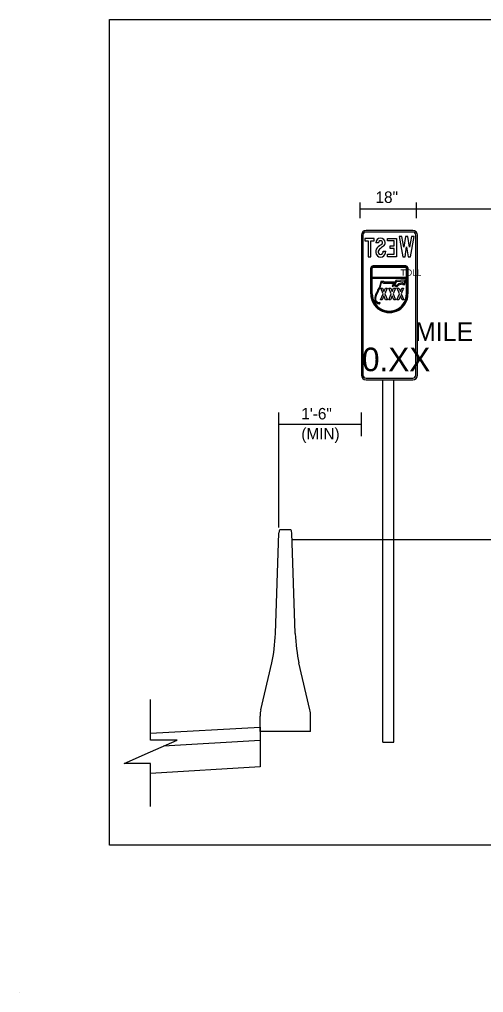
# Model space of a CAD drawing. Extents: x 57428 to 58066, y 11696 to 12105.
# Drawn here: x 57427.9 to 57541.3, y 11696.3 to 11934.3 of the extents above; entities that cross this region are included whole.
import ezdxf

# ---------------------------------------------------------------- set-up
doc = ezdxf.new("R2010")
doc.units = 0
for name, color, linetype in [('AdhocPoint_dp', 7, 'Continuous'), ('Default', 7, 'Continuous'), ('DimLines_dp', 7, 'Continuous'), ('NonPlottingEle_dp', 7, 'Continuous'), ('SignPanel', 7, 'Continuous'), ('TextMisc', 7, 'Continuous'), ('XSGrdLine_ex', 7, 'Continuous')]:
    doc.layers.add(name, color=color, linetype=linetype)

msp = doc.modelspace()

# ---------------------------------------------------------------- linework, layer by layer
at = {"layer": 'AdhocPoint_dp'}
msp.add_line((57427.89, 11696.32), (57427.89, 11696.32), dxfattribs=at)
at = {"layer": 'Default'}
msp.add_lwpolyline([(57459.93, 11741.8), (57459.93, 11752.36), (57453.47, 11752.36), (57459.93, 11755.17), (57466.39, 11757.99), (57459.93, 11757.99), (57459.93, 11767.99)], dxfattribs=at)
at = {"layer": 'DimLines_dp'}
for p, q in [((57511.19, 11885.65), (57511.19, 11889.48)), ((57511.19, 11887.93), (57524.88, 11887.93)), ((57524.88, 11885.65), (57524.88, 11889.48)), ((57524.88, 11887.93), (57585.54, 11887.93)), ((57491.3, 11810.03), (57491.3, 11838.14)), ((57511.44, 11832.39), (57511.44, 11838.14)), ((57491.3, 11835.3), (57511.44, 11835.3))]:
    msp.add_line(p, q, dxfattribs=at)
at = {"layer": 'NonPlottingEle_dp'}
for p, q in [((57516.7, 11807.11), (57516.7, 11846.15)), ((57519.36, 11807.11), (57519.36, 11846.15)), ((57516.7, 11757.53), (57516.7, 11807.11)), ((57519.36, 11757.53), (57519.36, 11807.11)), ((57516.7, 11757.53), (57519.36, 11757.53))]:
    msp.add_line(p, q, dxfattribs=at)
at = {"layer": 'SignPanel'}
for p, q in [((57515.59, 11879.64), (57514.97, 11879.64)), ((57515.59, 11879.64), (57514.97, 11879.64)), ((57515.59, 11879.64), (57514.97, 11879.64)), ((57516.78, 11877.63), (57517.41, 11877.63)), ((57516.78, 11877.63), (57517.41, 11877.63)), ((57516.78, 11877.63), (57517.41, 11877.63)), ((57513.72, 11867.13), (57513.72, 11873.41)), ((57513.91, 11867.13), (57513.91, 11873.41)), ((57514.1, 11871.13), (57514.1, 11873.41)), ((57522.27, 11873.98), (57514.29, 11873.98)), ((57522.27, 11873.79), (57514.29, 11873.79)), ((57522.27, 11873.6), (57514.29, 11873.6)), ((57522.47, 11871.13), (57522.47, 11873.41)), ((57522.65, 11867.13), (57522.65, 11873.41)), ((57522.84, 11867.13), (57522.84, 11873.41)), ((57522.47, 11871.13), (57514.1, 11871.13)), ((57514.1, 11867.13), (57514.1, 11870.94)), ((57522.47, 11870.94), (57514.1, 11870.94)), ((57522.47, 11867.13), (57522.47, 11870.94)), ((57515.84, 11868.76), (57515.38, 11868.04)), ((57515.61, 11867.97), (57516.05, 11868.67)), ((57516.17, 11870.19), (57515.84, 11868.76)), ((57516.05, 11868.67), (57516.35, 11869.97)), ((57516.9, 11870.19), (57516.17, 11870.19)), ((57516.35, 11869.97), (57516.78, 11869.97)), ((57516.78, 11869.97), (57516.89, 11869.81)), ((57516.89, 11869.81), (57519.89, 11869.81)), ((57517.01, 11870.04), (57516.9, 11870.19)), ((57519.74, 11870.04), (57517.01, 11870.04)), ((57519.44, 11869.52), (57518.94, 11869.18)), ((57518.94, 11869.18), (57519.07, 11868.99)), ((57519.07, 11868.99), (57519.45, 11869.25)), ((57520.05, 11869.16), (57519.44, 11869.52)), ((57519.45, 11869.25), (57520.08, 11868.88)), ((57519.87, 11870.39), (57519.74, 11870.04)), ((57522.25, 11870.57), (57519.87, 11870.39)), ((57519.89, 11869.81), (57520.03, 11870.17)), ((57520.03, 11870.17), (57521.98, 11870.32)), ((57520.5, 11869.58), (57520.05, 11869.16)), ((57520.08, 11868.88), (57520.62, 11869.37)), ((57521.42, 11869.88), (57520.5, 11869.58)), ((57520.62, 11869.37), (57521.38, 11869.62)), ((57520.99, 11870.23), (57520.99, 11870.23)), ((57521.38, 11869.62), (57521.63, 11869.42)), ((57521.69, 11869.66), (57521.42, 11869.88)), ((57521.63, 11869.42), (57522.08, 11869.48)), ((57521.88, 11869.69), (57521.69, 11869.66)), ((57521.98, 11870.32), (57521.88, 11869.69)), ((57522.08, 11869.48), (57522.25, 11870.57)), ((57514.97, 11867.18), (57514.72, 11866.26)), ((57514.72, 11866.26), (57514.72, 11865.39)), ((57514.95, 11866.23), (57515.19, 11867.09)), ((57514.95, 11865.5), (57514.95, 11866.23)), ((57515.38, 11867.85), (57514.97, 11867.18)), ((57515.19, 11867.09), (57515.61, 11867.79)), ((57515.38, 11868.04), (57515.38, 11867.85)), ((57515.61, 11867.79), (57515.61, 11867.97)), ((57514.72, 11865.39), (57515.47, 11864.78)), ((57515.58, 11864.99), (57514.95, 11865.5)), ((57515.47, 11864.78), (57515.83, 11864.69)), ((57515.79, 11864.94), (57515.58, 11864.99)), ((57515.93, 11865.04), (57515.79, 11864.94)), ((57515.83, 11864.69), (57516.06, 11864.85)), ((57516.06, 11864.85), (57515.93, 11865.04))]:
    msp.add_line(p, q, dxfattribs=at)
for points in [[(57523.99, 11882.65), (57512.58, 11882.65)], [(57511.44, 11881.51), (57511.44, 11847.29)], [(57511.82, 11881.51), (57511.82, 11847.29)], [(57523.99, 11882.27), (57512.58, 11882.27)], [(57524.75, 11847.29), (57524.75, 11881.51)], [(57525.13, 11847.29), (57525.13, 11881.51)], [(57512.58, 11846.53), (57523.99, 11846.53)], [(57512.58, 11846.15), (57523.99, 11846.15)]]:
    msp.add_lwpolyline(points, dxfattribs=at)
for points in [[(57513.73, 11880.09), (57514.55, 11880.09), (57514.55, 11880.72), (57512.29, 11880.72), (57512.29, 11880.09), (57513.11, 11880.09), (57513.11, 11876.22), (57513.73, 11876.22)], [(57513.73, 11880.09), (57514.55, 11880.09), (57514.55, 11880.72), (57512.29, 11880.72), (57512.29, 11880.09), (57513.11, 11880.09), (57513.11, 11876.22), (57513.73, 11876.22)], [(57513.73, 11880.09), (57514.55, 11880.09), (57514.55, 11880.72), (57512.29, 11880.72), (57512.29, 11880.09), (57513.11, 11880.09), (57513.11, 11876.22), (57513.73, 11876.22)], [(57519.44, 11876.85), (57519.44, 11878.29), (57518.46, 11878.29), (57518.46, 11878.92), (57519.44, 11878.92), (57519.44, 11880.09), (57517.79, 11880.09), (57517.79, 11880.72), (57520.06, 11880.72), (57520.06, 11876.22), (57517.79, 11876.22), (57517.79, 11876.85)], [(57519.44, 11876.85), (57519.44, 11878.29), (57518.46, 11878.29), (57518.46, 11878.92), (57519.44, 11878.92), (57519.44, 11880.09), (57517.79, 11880.09), (57517.79, 11880.72), (57520.06, 11880.72), (57520.06, 11876.22), (57517.79, 11876.22), (57517.79, 11876.85)], [(57519.44, 11876.85), (57519.44, 11878.29), (57518.46, 11878.29), (57518.46, 11878.92), (57519.44, 11878.92), (57519.44, 11880.09), (57517.79, 11880.09), (57517.79, 11880.72), (57520.06, 11880.72), (57520.06, 11876.22), (57517.79, 11876.22), (57517.79, 11876.85)], [(57523.22, 11878.61), (57522.81, 11881.17), (57522.21, 11881.17), (57521.81, 11878.61), (57521.35, 11881.17), (57520.66, 11881.17), (57521.54, 11876.22), (57522.12, 11876.22), (57522.51, 11878.69), (57522.9, 11876.22), (57523.49, 11876.22), (57524.37, 11881.17), (57523.67, 11881.17)], [(57523.22, 11878.61), (57522.81, 11881.17), (57522.21, 11881.17), (57521.81, 11878.61), (57521.35, 11881.17), (57520.66, 11881.17), (57521.54, 11876.22), (57522.12, 11876.22), (57522.51, 11878.69), (57522.9, 11876.22), (57523.49, 11876.22), (57524.37, 11881.17), (57523.67, 11881.17)], [(57523.22, 11878.61), (57522.81, 11881.17), (57522.21, 11881.17), (57521.81, 11878.61), (57521.35, 11881.17), (57520.66, 11881.17), (57521.54, 11876.22), (57522.12, 11876.22), (57522.51, 11878.69), (57522.9, 11876.22), (57523.49, 11876.22), (57524.37, 11881.17), (57523.67, 11881.17)], [(57517.36, 11865.71), (57516.95, 11866.69), (57516.55, 11865.71), (57516.12, 11865.71), (57516.74, 11867.2), (57516.17, 11868.57), (57516.6, 11868.57), (57516.95, 11867.71), (57517.31, 11868.57), (57517.74, 11868.57), (57517.17, 11867.2), (57517.79, 11865.71)], [(57519.38, 11865.71), (57518.97, 11866.69), (57518.56, 11865.71), (57518.13, 11865.71), (57518.76, 11867.2), (57518.18, 11868.57), (57518.61, 11868.57), (57518.97, 11867.71), (57519.33, 11868.57), (57519.75, 11868.57), (57519.18, 11867.2), (57519.8, 11865.71)], [(57521.39, 11865.71), (57520.99, 11866.69), (57520.58, 11865.71), (57520.15, 11865.71), (57520.77, 11867.2), (57520.2, 11868.57), (57520.63, 11868.57), (57520.99, 11867.71), (57521.34, 11868.57), (57521.77, 11868.57), (57521.2, 11867.2), (57521.82, 11865.71)]]:
    msp.add_lwpolyline(points, close=True, dxfattribs=at)
for centre, radius, start, end in [((57512.58, 11881.51), 1.14, 90, 180), ((57523.99, 11881.51), 1.14, 0, 90), ((57512.58, 11881.51), 0.76, 90, 180), ((57523.99, 11881.51), 0.76, 0, 90), ((57512.58, 11847.29), 1.14, 180, 270), ((57512.58, 11847.29), 0.76, 180, 270), ((57523.99, 11847.29), 1.14, 270, 0), ((57523.99, 11847.29), 0.76, 270, 0)]:
    msp.add_arc(centre, radius, start, end, dxfattribs=at)
for centre, major_axis, ratio, start_param, end_param in [((57516.12, 11879.61), (0, -1.17), 0.981197, 1.634182, 4.688511), ((57516.12, 11879.61), (0, -1.17), 0.981197, 1.634182, 4.688511), ((57516.12, 11879.61), (0, -1.17), 0.981197, 1.634182, 4.688511), ((57516.32, 11877.45), (0, -1.4), 0.981197, 3.939023, 5.163791), ((57516.32, 11877.45), (0, -1.4), 0.981197, 3.939023, 5.163791), ((57516.32, 11877.45), (0, -1.4), 0.981197, 3.939023, 5.163791), ((57518.44, 11875.47), (0, -4.32), 0.981197, 3.642536, 3.961892), ((57518.44, 11875.47), (0, -4.32), 0.981197, 3.642536, 3.961892), ((57518.44, 11875.47), (0, -4.32), 0.981197, 3.642536, 3.961892), ((57516.33, 11877.45), (0, -0.78), 0.981197, 3.79238, 5.170369), ((57516.33, 11877.45), (0, -0.78), 0.981197, 3.79238, 5.170369), ((57516.33, 11877.45), (0, -0.78), 0.981197, 3.79238, 5.170369), ((57516.13, 11879.6), (0, -0.55), 0.981197, 2.28404, 4.637874), ((57516.13, 11879.6), (0, -0.55), 0.981197, 2.28404, 4.637874), ((57516.13, 11879.6), (0, -0.55), 0.981197, 2.28404, 4.637874), ((57518.97, 11874.79), (0, -4.56), 0.981197, 3.63779, 3.909641), ((57518.97, 11874.79), (0, -4.56), 0.981197, 3.63779, 3.909641), ((57518.97, 11874.79), (0, -4.56), 0.981197, 3.63779, 3.909641), ((57516.19, 11879.67), (0, -0.453), 0.981197, 0.484634, 2.267813), ((57516.19, 11879.67), (0, -0.453), 0.981197, 0.484634, 2.267813), ((57516.19, 11879.67), (0, -0.453), 0.981197, 0.484634, 2.267813), ((57516.24, 11879.65), (0, -1.05), 0.981197, 0.629826, 1.606762), ((57516.24, 11879.65), (0, -1.05), 0.981197, 0.629826, 1.606762), ((57516.24, 11879.65), (0, -1.05), 0.981197, 0.629826, 1.606762), ((57516.16, 11877.38), (0, -1.23), 0.981197, 5.173086, 6.638731), ((57516.16, 11877.38), (0, -1.23), 0.981197, 5.173086, 6.638731), ((57516.16, 11877.38), (0, -1.23), 0.981197, 5.173086, 6.638731), ((57516.14, 11877.37), (0, -0.572), 0.981197, 5.194718, 7.162991), ((57516.14, 11877.37), (0, -0.572), 0.981197, 5.194718, 7.162991), ((57516.14, 11877.37), (0, -0.572), 0.981197, 5.194718, 7.162991), ((57515.9, 11877.59), (0, -0.897), 0.981197, 0.859453, 1.616836), ((57515.9, 11877.59), (0, -0.897), 0.981197, 0.859453, 1.616836), ((57515.9, 11877.59), (0, -0.897), 0.981197, 0.859453, 1.616836), ((57515.96, 11877.56), (0, -1.47), 0.981197, 0.439911, 1.615229), ((57515.96, 11877.56), (0, -1.47), 0.981197, 0.439911, 1.615229), ((57515.96, 11877.56), (0, -1.47), 0.981197, 0.439911, 1.615229), ((57514.29, 11873.41), (0, 0.57), 0.9997, 0, 1.570796), ((57514.29, 11873.41), (0, 0.38), 0.9997, 0, 1.570796), ((57514.29, 11873.41), (0, 0.19), 0.9997, 0, 1.570796), ((57522.27, 11873.41), (0, 0.57), 0.9997, 4.712389, 6.283185), ((57522.27, 11873.41), (0, 0.38), 0.9997, 4.712389, 6.283185), ((57522.27, 11873.41), (0, 0.19), 0.9997, 4.712389, 6.283185), ((57518.28, 11867.13), (0, 4.56), 0.9997, 1.570796, 4.712389), ((57518.28, 11867.13), (0, 4.37), 0.9997, 1.570796, 4.712389), ((57518.28, 11867.13), (0, 4.18), 0.9997, 1.570796, 4.712389)]:
    msp.add_ellipse(centre, major_axis=major_axis, ratio=ratio, start_param=start_param, end_param=end_param, dxfattribs=at)
at = {"layer": 'TextMisc'}
msp.add_lwpolyline([(57449.89, 11934.25), (57709.55, 11934.25), (57709.55, 11732.32), (57449.89, 11732.32)], close=True, dxfattribs=at)
at = {"layer": 'XSGrdLine_ex'}
for p, q in [((57494.17, 11809.43), (57491.55, 11809.43)), ((57490.43, 11784.12), (57491.3, 11808.74)), ((57495.29, 11784.12), (57494.43, 11808.74)), ((57494.48, 11807.11), (57616.18, 11807.11)), ((57486.86, 11765.45), (57489.53, 11776.9)), ((57498.86, 11765.45), (57496.19, 11776.9)), ((57486.7, 11760.13), (57486.7, 11763.91)), ((57499.02, 11760.13), (57499.02, 11763.91)), ((57459.93, 11759.71), (57486.7, 11761.2)), ((57486.7, 11761.2), (57486.7, 11760.13)), ((57499.02, 11760.13), (57486.7, 11760.13)), ((57486.7, 11760.13), (57486.7, 11751.48)), ((57486.7, 11757.95), (57463.05, 11756.53)), ((57486.7, 11751.48), (57459.93, 11749.87))]:
    msp.add_line(p, q, dxfattribs=at)
for centre, major_axis, start_param, end_param in [((57491.55, 11808.66), (0, 0.77), 0, 1.465919), ((57494.17, 11808.66), (0, 0.77), 4.817266, 6.283185), ((57485.33, 11785.73), (0, -15.4), 0.96007, 1.465919), ((57500.4, 11785.73), (0, -15.4), 4.817266, 5.323115), ((57487.6, 11763.91), (0, 2.7), 0.96007, 1.570796), ((57498.12, 11763.91), (0, 2.7), 4.712389, 5.323115)]:
    msp.add_ellipse(centre, major_axis=major_axis, ratio=0.333333, start_param=start_param, end_param=end_param, dxfattribs=at)

# ---------------------------------------------------------------- texts
at = {"layer": 'DimLines_dp'}
for s, p in [('18"', (57514.9, 11889.4)), ('1\'-6"', (57496.77, 11836.46)), ('(MIN)', (57496.77, 11831.56))]:
    msp.add_text(s, height=2.8, dxfattribs=at).set_placement(p)
at = {"layer": 'SignPanel'}
for s, height, p in [('TOLL', 1.519, (57521.04, 11871.6)), ('MILE', 4.562, (57524.54, 11855.65)), ('0.XX', 5.75, (57511.61, 11848.25))]:
    msp.add_text(s, height=height, rotation=360, dxfattribs=at).set_placement(p)

doc.saveas('drawing.dxf')
